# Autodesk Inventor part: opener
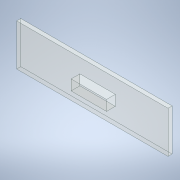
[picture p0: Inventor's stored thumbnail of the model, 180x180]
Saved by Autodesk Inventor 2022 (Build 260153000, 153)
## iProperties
Created: 2021-07
Part Number: opener
Material: Glass
Document SubType Name: Modeling
Designer: USER
Density: 2.18 g/cm^3
Appearance: Clear
Author: USER
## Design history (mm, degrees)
sketch "Sketch1"
  geometry: L1 (0, 0)-(257.632, 0); L2 (257.632, 0)-(257.632, -71); L3 (257.632, -71)-(0, -71); L4 (0, -71)-(0, 0)
  constraints: 8 end point, 2 parallel, 1 horizontal, 1 perpendicular
  dimensions: "d0" = 257.632 distance of L2.end L3.end; "d1" = 71 distance of L1.end L2.end
extrude "Extrusion1" new body sketch "Sketch1" distance "d2" = 7; taper "d3" = 0 deg
sketch "Sketch2"
  geometry: L1 (107.598, -24.309)-(167.986, -24.309); L2 (167.986, -24.309)-(167.986, -41.964); L3 (167.986, -41.964)-(107.598, -41.964); L4 (107.598, -41.964)-(107.598, -24.309); 1 further point
  constraints: 8 end point, 2 parallel, 1 horizontal, 1 perpendicular
extrude "Extrusion2" join sketch "Sketch2" distance "d4" = 15; taper "d5" = 0 deg
body "Solid1"
